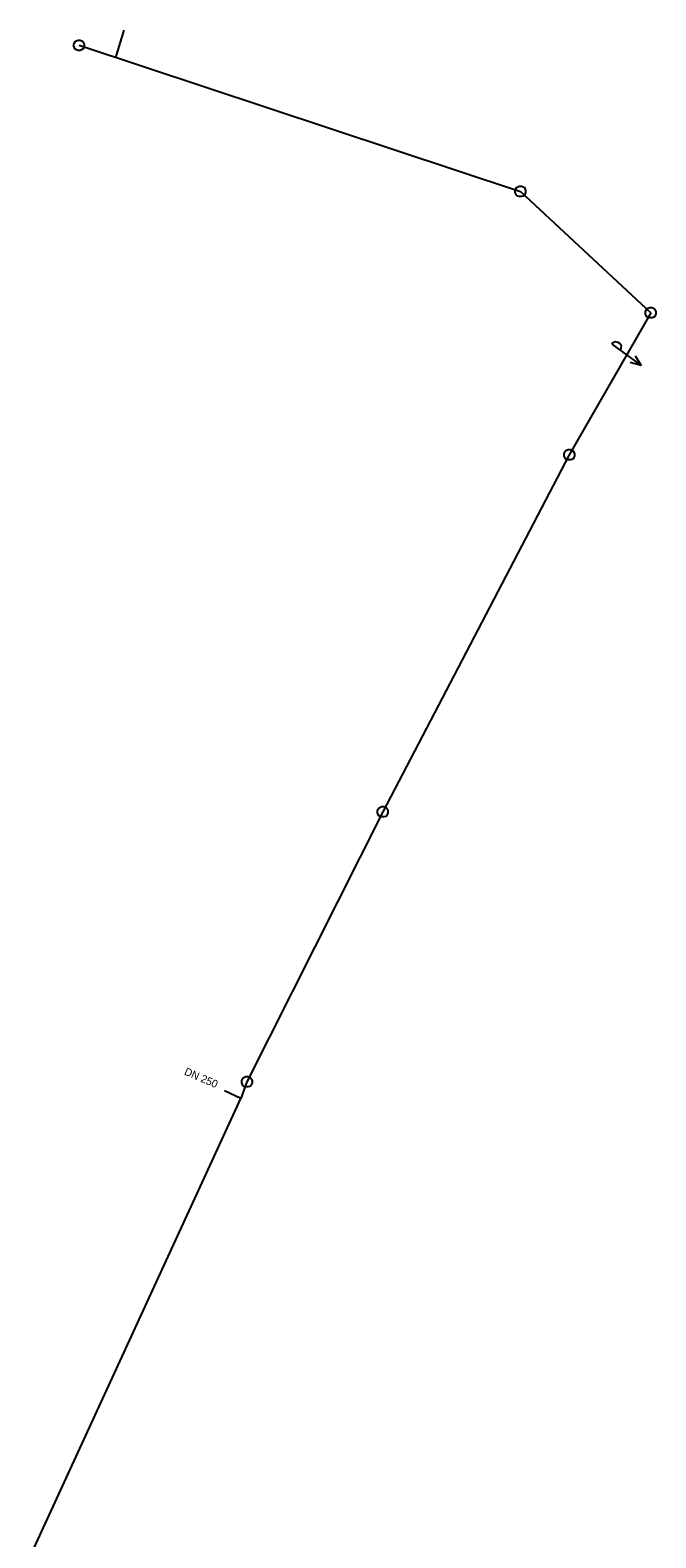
# Model space of a CAD drawing. Extents: x -717256 to -716843, y -1145423 to -1142840.
# Drawn here: x -717205.2 to -717144.5, y -1143905.3 to -1143759.1 of the extents above; entities that cross this region are included whole.
import ezdxf

# ---------------------------------------------------------------- set-up
doc = ezdxf.new("R2010")
doc.units = 0
for name, color, linetype in [('Vrstva 30', 7, 'Continuous'), ('Vrstva 31', 7, 'Continuous'), ('Vrstva 9', 7, 'Continuous')]:
    doc.layers.add(name, color=color, linetype=linetype)

msp = doc.modelspace()

# ---------------------------------------------------------------- linework, layer by layer
at = {"layer": 'Vrstva 30'}
for p, q in [((-717200.973, -1143760.425), (-717200.923, -1143760.275)), ((-717200.973, -1143760.625), (-717200.973, -1143760.425)), ((-717200.873, -1143760.875), (-717200.973, -1143760.625)), ((-717200.923, -1143760.275), (-717200.823, -1143760.125)), ((-717200.723, -1143760.975), (-717200.873, -1143760.875)), ((-717200.823, -1143760.125), (-717200.573, -1143760.025)), ((-717200.573, -1143761.025), (-717200.723, -1143760.975)), ((-717200.573, -1143760.025), (-717200.373, -1143760.025)), ((-717200.373, -1143761.025), (-717200.573, -1143761.025)), ((-717200.473, -1143760.525), (-717157.641, -1143774.704)), ((-717200.373, -1143760.025), (-717200.123, -1143760.125)), ((-717200.223, -1143760.975), (-717200.373, -1143761.025)), ((-717200.073, -1143760.875), (-717200.223, -1143760.975)), ((-717200.123, -1143760.125), (-717200.023, -1143760.275)), ((-717199.973, -1143760.625), (-717200.073, -1143760.875)), ((-717200.023, -1143760.275), (-717199.973, -1143760.425)), ((-717199.973, -1143760.425), (-717199.973, -1143760.625)), ((-717158.091, -1143774.454), (-717157.991, -1143774.304)), ((-717157.991, -1143774.304), (-717157.741, -1143774.204)), ((-717157.741, -1143774.204), (-717157.541, -1143774.204)), ((-717157.541, -1143774.204), (-717157.291, -1143774.304)), ((-717157.291, -1143774.304), (-717157.191, -1143774.454)), ((-717158.141, -1143774.604), (-717158.091, -1143774.454)), ((-717158.141, -1143774.804), (-717158.141, -1143774.604)), ((-717158.041, -1143775.054), (-717158.141, -1143774.804)), ((-717157.891, -1143775.154), (-717158.041, -1143775.054)), ((-717157.741, -1143775.204), (-717157.891, -1143775.154)), ((-717157.541, -1143775.204), (-717157.741, -1143775.204)), ((-717157.641, -1143774.704), (-717145.002, -1143786.467)), ((-717157.391, -1143775.154), (-717157.541, -1143775.204)), ((-717157.241, -1143775.054), (-717157.391, -1143775.154)), ((-717157.141, -1143774.804), (-717157.241, -1143775.054)), ((-717157.191, -1143774.454), (-717157.141, -1143774.604)), ((-717157.141, -1143774.604), (-717157.141, -1143774.804)), ((-717145.352, -1143786.067), (-717145.102, -1143785.967)), ((-717145.102, -1143785.967), (-717144.902, -1143785.967)), ((-717144.902, -1143785.967), (-717144.652, -1143786.067)), ((-717145.002, -1143786.467), (-717152.902, -1143800.241)), ((-717145.502, -1143786.367), (-717145.452, -1143786.217)), ((-717145.502, -1143786.567), (-717145.502, -1143786.367)), ((-717145.402, -1143786.817), (-717145.502, -1143786.567)), ((-717145.452, -1143786.217), (-717145.352, -1143786.067)), ((-717145.252, -1143786.917), (-717145.402, -1143786.817)), ((-717145.102, -1143786.967), (-717145.252, -1143786.917)), ((-717144.902, -1143786.967), (-717145.102, -1143786.967)), ((-717144.752, -1143786.917), (-717144.902, -1143786.967)), ((-717144.602, -1143786.817), (-717144.752, -1143786.917)), ((-717144.652, -1143786.067), (-717144.552, -1143786.217)), ((-717144.502, -1143786.567), (-717144.602, -1143786.817)), ((-717144.552, -1143786.217), (-717144.502, -1143786.367)), ((-717144.502, -1143786.367), (-717144.502, -1143786.567)), ((-717152.902, -1143800.241), (-717171, -1143834.869)), ((-717153.402, -1143800.141), (-717153.352, -1143799.991)), ((-717153.402, -1143800.341), (-717153.402, -1143800.141)), ((-717153.302, -1143800.591), (-717153.402, -1143800.341)), ((-717153.352, -1143799.991), (-717153.252, -1143799.841)), ((-717153.152, -1143800.691), (-717153.302, -1143800.591)), ((-717153.252, -1143799.841), (-717153.002, -1143799.741)), ((-717153.002, -1143799.741), (-717152.802, -1143799.741)), ((-717152.802, -1143799.741), (-717152.552, -1143799.841)), ((-717152.502, -1143800.591), (-717152.652, -1143800.691)), ((-717152.552, -1143799.841), (-717152.452, -1143799.991)), ((-717152.402, -1143800.341), (-717152.502, -1143800.591)), ((-717152.452, -1143799.991), (-717152.402, -1143800.141)), ((-717152.402, -1143800.141), (-717152.402, -1143800.341)), ((-717153.002, -1143800.741), (-717153.152, -1143800.691)), ((-717152.802, -1143800.741), (-717153.002, -1143800.741)), ((-717152.652, -1143800.691), (-717152.802, -1143800.741)), ((-717171, -1143834.869), (-717184.188, -1143861.055)), ((-717171.5, -1143834.769), (-717171.45, -1143834.619)), ((-717171.5, -1143834.969), (-717171.5, -1143834.769)), ((-717171.4, -1143835.219), (-717171.5, -1143834.969)), ((-717171.45, -1143834.619), (-717171.35, -1143834.469)), ((-717171.25, -1143835.319), (-717171.4, -1143835.219)), ((-717171.35, -1143834.469), (-717171.1, -1143834.369)), ((-717171.1, -1143835.369), (-717171.25, -1143835.319)), ((-717171.1, -1143834.369), (-717170.9, -1143834.369)), ((-717170.9, -1143835.369), (-717171.1, -1143835.369)), ((-717170.9, -1143834.369), (-717170.65, -1143834.469)), ((-717170.75, -1143835.319), (-717170.9, -1143835.369)), ((-717170.6, -1143835.219), (-717170.75, -1143835.319)), ((-717170.65, -1143834.469), (-717170.55, -1143834.619)), ((-717170.5, -1143834.969), (-717170.6, -1143835.219)), ((-717170.55, -1143834.619), (-717170.5, -1143834.769)), ((-717170.5, -1143834.769), (-717170.5, -1143834.969)), ((-717184.538, -1143860.655), (-717184.288, -1143860.555)), ((-717184.288, -1143860.555), (-717184.088, -1143860.555)), ((-717184.088, -1143860.555), (-717183.838, -1143860.655)), ((-717184.759, -1143862.68), (-717186.358, -1143861.938)), ((-717184.188, -1143861.055), (-717184.759, -1143862.68)), ((-717184.688, -1143860.955), (-717184.638, -1143860.805)), ((-717184.688, -1143861.155), (-717184.688, -1143860.955)), ((-717184.588, -1143861.405), (-717184.688, -1143861.155)), ((-717184.638, -1143860.805), (-717184.538, -1143860.655)), ((-717184.438, -1143861.505), (-717184.588, -1143861.405)), ((-717184.288, -1143861.555), (-717184.438, -1143861.505)), ((-717184.088, -1143861.555), (-717184.288, -1143861.555)), ((-717183.938, -1143861.505), (-717184.088, -1143861.555)), ((-717183.788, -1143861.405), (-717183.938, -1143861.505)), ((-717183.838, -1143860.655), (-717183.738, -1143860.805)), ((-717183.688, -1143861.155), (-717183.788, -1143861.405)), ((-717183.738, -1143860.805), (-717183.688, -1143860.955)), ((-717183.688, -1143860.955), (-717183.688, -1143861.155)), ((-717205.219, -1143907.108), (-717184.759, -1143862.68))]:
    msp.add_line(p, q, dxfattribs=at)
at = {"layer": 'Vrstva 31'}
msp.add_line((-717196.898, -1143761.708), (-717196.09, -1143759.061), dxfattribs=at)
at = {"layer": 'Vrstva 9'}
for p, q in [((-717148.711, -1143789.431), (-717148.769, -1143789.512)), ((-717148.769, -1143789.512), (-717145.938, -1143791.569)), ((-717148.582, -1143789.339), (-717148.711, -1143789.431)), ((-717148.413, -1143789.276), (-717148.582, -1143789.339)), ((-717148.152, -1143789.342), (-717148.413, -1143789.276)), ((-717147.99, -1143789.46), (-717148.152, -1143789.342)), ((-717147.847, -1143789.688), (-717147.99, -1143789.46)), ((-717147.96, -1143790.1), (-717147.901, -1143790.019)), ((-717147.901, -1143790.019), (-717147.854, -1143789.868)), ((-717147.854, -1143789.868), (-717147.847, -1143789.688)), ((-717145.938, -1143791.569), (-717146.982, -1143791.305)), ((-717146.512, -1143790.658), (-717145.938, -1143791.569))]:
    msp.add_line(p, q, dxfattribs=at)

# ---------------------------------------------------------------- texts
at = {"layer": 'Vrstva 30'}
msp.add_text('DN 250', height=0.75, rotation=336.6, dxfattribs=at).set_placement((-717190.33, -1143860.332))

doc.saveas('drawing.dxf')
